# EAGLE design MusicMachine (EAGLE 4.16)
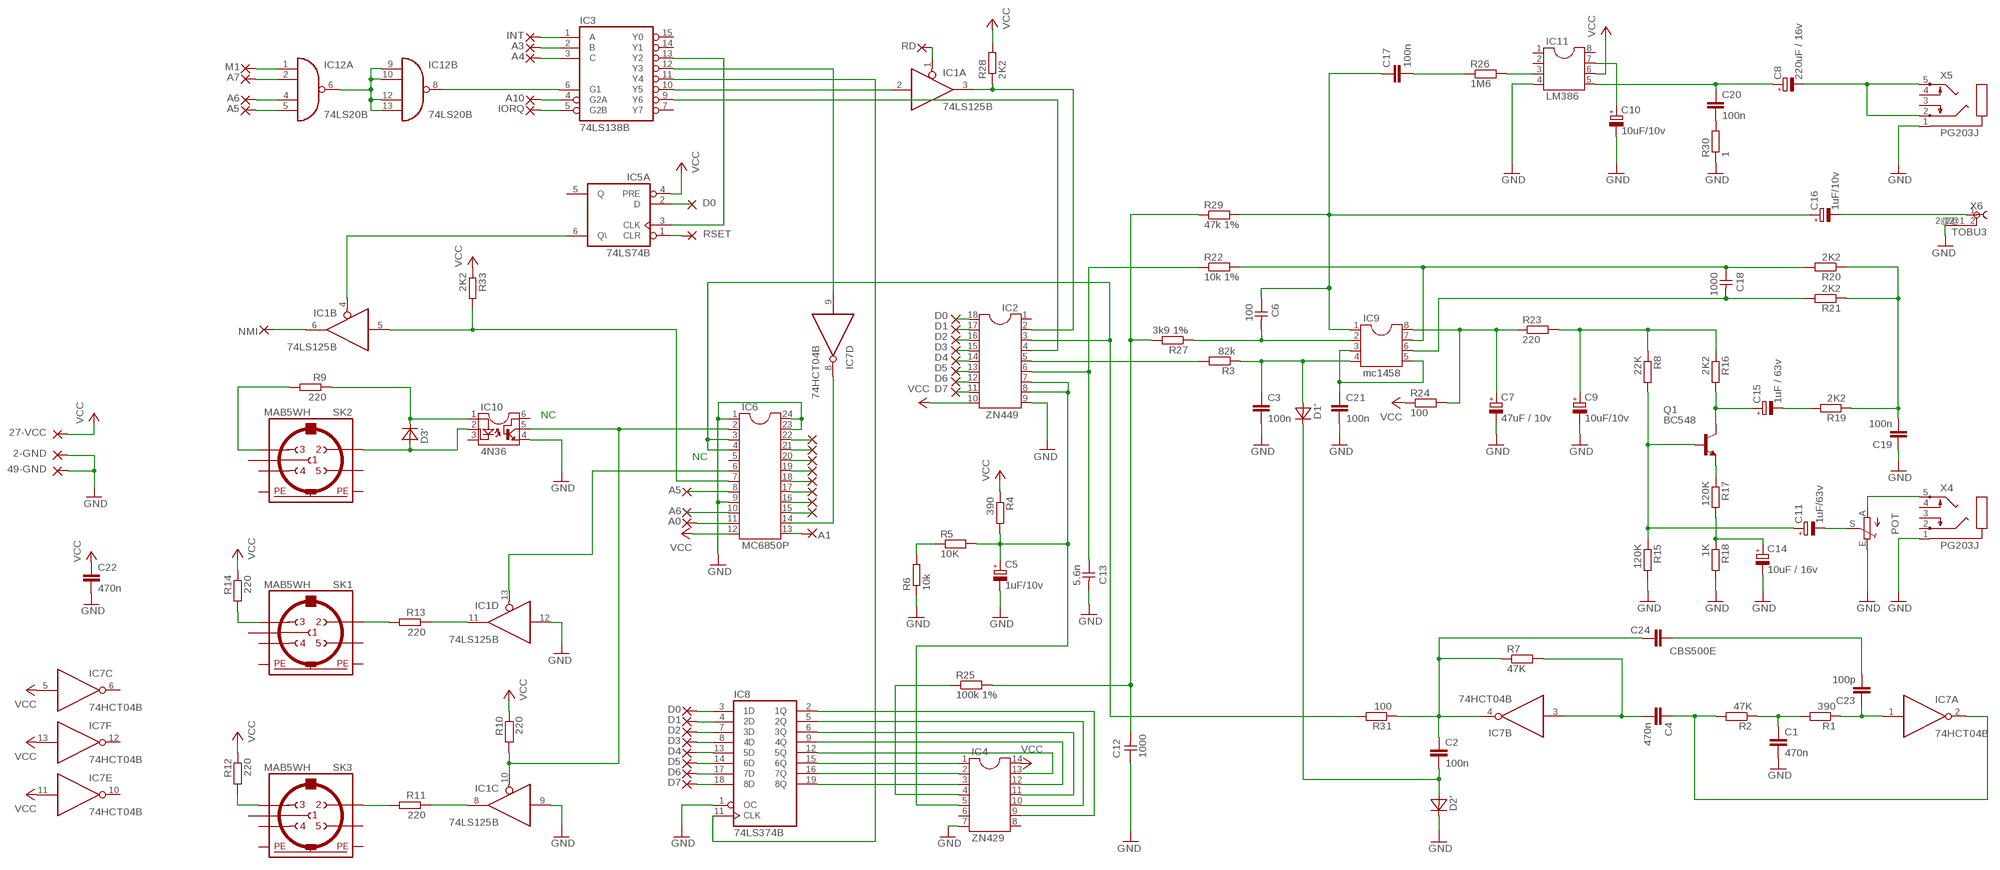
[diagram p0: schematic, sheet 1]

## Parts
2-GND  SMD2  [SMD1,27-2,54]
27-VCC  SMD2  [SMD1,27-2,54]
49-GND  SMD2  [SMD1,27-2,54]
A0  SMD2  [SMD1,27-2,54]
A1  SMD2  [SMD1,27-2,54]
A3  SMD2  [SMD1,27-2,54]
A4  SMD2  [SMD1,27-2,54]
A5  SMD2  [SMD1,27-2,54]
A6  SMD2  [SMD1,27-2,54]
A7  SMD2  [SMD1,27-2,54]
A10  SMD2  [SMD1,27-2,54]
C1  470n  C-EU050-024X044  [C050-024X044]
C2  100n  C-EU050-024X044  [C050-024X044]
C3  100n  C-EU050-024X044  [C050-024X044]
C4  470n  C-EU050-024X044  [C050-024X044]
C5  1uF/10v  CPOL-EUE2.5-5  [E2,5-5]
C6  100  CAPNP-12  [C-12]
C7  47uF / 10v  CPOL-EUE2.5-5  [E2,5-5]
C8  220uF / 16v  CPOL-EUE5-6  [E5-6]
C9  10uF/10v  CPOL-EUE2.5-5  [E2,5-5]
C10  10uF/10v  CPOL-EUE2.5-5  [E2,5-5]
C11  1uF/63v  CPOL-EUE2.5-5  [E2,5-5]
C12  1000  CAPNP-12  [C-12]
C13  5.6n  CAPNP-15  [C-15]
C14  10uF / 16v  CPOL-EUE2.5-5  [E2,5-5]
C15  1uF / 63v  CPOL-EUE2.5-5  [E2,5-5]
C16  1uF/10v  CPOL-EUE2.5-5  [E2,5-5]
C17  100n  C-EU050-024X044  [C050-024X044]
C18  1000  CAPNP-12  [C-12]
C19  100n  C-EU050-024X044  [C050-024X044]
C20  100n  C-EU050-024X044  [C050-024X044]
C21  100n  C-EU050-024X044  [C050-024X044]
C22  470n  C-EU050-024X044  [C050-024X044]
C23  100p  C-EU050-024X044  [C050-024X044]
C24  CBS500E  C-EU050-024X044  [C050-024X044]
D0  SMD2  [SMD1,27-2,54]
D1  SMD2  [SMD1,27-2,54]
D1'  DIODE-10/2  [D-10/2]
D2  SMD2  [SMD1,27-2,54]
D2'  DIODE-10/2  [D-10/2]
D3  SMD2  [SMD1,27-2,54]
D3'  DIODE-10/2  [D-10/2]
D4  SMD2  [SMD1,27-2,54]
D5  SMD2  [SMD1,27-2,54]
D6  SMD2  [SMD1,27-2,54]
D7  SMD2  [SMD1,27-2,54]
IC1  74LS125B  [DIL14-B]
IC2  ZN449  DIL18B  [DIL18B]
IC3  74LS138B  [DIL16-B]
IC4  ZN429  DIL14  [DIL14]
IC5  74LS74B  [DIL14-B]
IC6  MC6850P  DIL24/6B  [DIL24-6B]
IC7  74HCT04B  74LS04B  [DIL14-B]
IC8  74LS374B  [DIL20-B]
IC9  mc1458  DIL8  [DIL08]
IC10  4N36  DIL6  [DIL06]
IC11  LM386  DIL8  [DIL08]
IC12  74LS20B  [DIL14-B]
INT  SMD2  [SMD1,27-2,54]
IORQ  SMD2  [SMD1,27-2,54]
M1  SMD2  [SMD1,27-2,54]
NMI  SMD2  [SMD1,27-2,54]
POT  TRIM_EU-LI15  [LI15]
Q1  BC548  [TO92-EBC]
R1  390  R-EU_0207/10  [0207/10]
R2  47K  R-EU_0207/12  [0207/12]
R3  82k  R-EU_0207/12  [0207/12]
R4  390  R-EU_0207/12  [0207/12]
R5  10K  R-EU_0207/12  [0207/12]
R6  10k  R-EU_0207/12  [0207/12]
R7  47K  R-EU_0207/12  [0207/12]
R8  22K  R-EU_0207/12  [0207/12]
R9  220  R-EU_0207/12  [0207/12]
R10  220  R-EU_0207/12  [0207/12]
R11  220  R-EU_0207/12  [0207/12]
R12  220  R-EU_0207/12  [0207/12]
R13  220  R-EU_0207/12  [0207/12]
R14  220  R-EU_0207/12  [0207/12]
R15  120K  R-EU_0207/12  [0207/12]
R16  2K2  R-EU_0207/12  [0207/12]
R17  120K  R-EU_0207/12  [0207/12]
R18  1K  R-EU_0207/12  [0207/12]
R19  2K2  R-EU_0207/12  [0207/12]
R20  2K2  R-EU_0207/12  [0207/12]
R21  2K2  R-EU_0207/12  [0207/12]
R22  10k 1%  R-EU_0207/12  [0207/12]
R23  220  R-EU_0207/12  [0207/12]
R24  100  R-EU_0207/12  [0207/12]
R25  100k 1%  R-EU_0207/12  [0207/12]
R26  1M6  R-EU_0207/10  [0207/10]
R27  3k9 1%  R-EU_0207/12  [0207/12]
R28  2K2  R-EU_0207/12  [0207/12]
R29  47k 1%  R-EU_0207/12  [0207/12]
R30  1  R-EU_0207/12  [0207/12]
R31  100  R-EU_0207/12  [0207/12]
R33  2K2  R-EU_0207/12  [0207/12]
RD  SMD2  [SMD1,27-2,54]
RSET  SMD2  [SMD1,27-2,54]
SK1  MAB5WH  [MAB5WH]
SK2  MAB5WH  [MAB5WH]
SK3  MAB5WH  [MAB5WH]
X4  PG203J  [PG203J]
X5  PG203J  [PG203J]
X6  TOBU3  [TOBU3]

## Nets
A0: A0.1(P) IC6.11
A1: A1.1(P) IC6.13
A3: A3.1(P) IC3.2(B)
A4: A4.1(P) IC3.3(C)
A5: A5.1(P) IC6.8 IC12.5(A:I3)
A6: A6.1(P) IC6.10 IC12.4(A:I2)
A7: A7.1(P) IC12.2(A:I1)
A10: A10.1(P) IC3.4(G2A)
D0: D0.1(P) IC2.18 IC5.2(A:D) IC6.22 IC8.3(1D)
D1: D1.1(P) IC2.17 IC6.21 IC8.4(2D)
D2: D2.1(P) IC2.16 IC6.20 IC8.7(3D)
D3: D3.1(P) IC2.15 IC6.19 IC8.8(4D)
D4: D4.1(P) IC2.14 IC6.18 IC8.13(5D)
D5: D5.1(P) IC2.13 IC6.17 IC8.14(6D)
D6: D6.1(P) IC2.12 IC6.16 IC8.17(7D)
D7: D7.1(P) IC2.11 IC6.15 IC8.18(8D)
GND: 2-GND.1(P) 49-GND.1(P) C1.2 C3.2 C5.- C7.- C9.- C10.- C12.P$1 C13.2 C14.- C19.1 C21.2 C22.2 D2'.P$4(K) IC1.9(C:I) IC1.12(D:I) IC2.9 IC4.7 IC6.1 IC6.9 IC6.23 IC6.24 IC8.1(OC) IC10.4 IC11.4 POT.E R6.1 R15.2 R18.2 R30.1 X4.1 X5.1 X6.2@2
INT: IC3.1(A) INT.1(P)
IORQ: IC3.5(G2B) IORQ.1(P)
M1: IC12.1(A:I0) M1.1(P)
N$3: IC6.14 IC7.8(D:O)
N$5: C4.1 IC7.2(A:O) R2.2
N$6: C5.+ IC2.7 IC2.8 IC4.5 R4.2 R5.2
N$7: IC12.6(A:O) IC12.9(B:I0) IC12.10(B:I1) IC12.12(B:I2) IC12.13(B:I3)
N$8: C13.1 IC2.6 R22.1
N$9: IC3.6(G1) IC12.8(B:O)
N$11: IC2.4 IC3.9(Y6)
N$12: IC1.2(A:I) IC3.10(Y5)
N$14: IC3.11(Y4) IC8.11(CLK)
N$15: R9.2 SK2.3
N$17: IC3.12(Y3) IC7.9(D:I)
N$22: C23.1 IC7.1(A:I) R1.1
N$23: C23.2 C24.2
N$24: C1.1 R1.2 R2.1
N$25: C2.1 C24.1 IC7.4(B:O) R7.1 R31.1
N$26: IC1.10(C:OE) IC6.2 IC10.5 R10.2
N$27: C4.2 IC7.3(B:I) R7.2
N$28: IC2.3 IC6.3 IC6.4 R31.2
N$29: IC1.13(D:OE) IC6.6
N$30: IC1.5(B:I) IC6.7 R33.2
N$31: IC3.13(Y2) IC5.3(A:CLK)
N$32: IC1.4(B:OE) IC5.6(A:Q\)
N$33: IC1.1(A:OE) RD.1(P)
N$34: IC1.3(A:O) IC2.2 R28.1
N$35: R12.2 SK3.3
N$36: IC4.1 IC8.15(6Q)
N$37: IC2.5 R3.2
N$38: C3.1 D1'.P$3(A) IC9.4 R3.1
N$39: IC4.2 IC8.16(7Q)
N$40: IC4.3 IC8.19(8Q)
N$41: IC4.11 IC8.6(3Q)
N$42: IC4.9 IC8.2(1Q)
N$43: IC4.10 IC8.5(2Q)
N$44: IC4.12 IC8.9(4Q)
N$45: C12.P$2 R25.2 R27.2 R29.1
N$46: IC4.13 IC8.12(5Q)
N$47: IC4.4 R25.1
N$48: C6.P$1 C16.+ C17.1 IC9.1 R29.2
N$49: R5.1 R6.2
N$50: C16.- X6.1
N$51: R14.2 SK1.3
N$52: R13.2 SK1.2
N$53: IC1.11(D:O) R13.1
N$54: IC1.8(C:O) R11.1
N$55: R11.2 SK3.2
N$57: IC1.6(B:O) NMI.1(P)
N$58: D3'.P$4(K) IC10.1 R9.1
N$59: D3'.P$3(A) IC10.2 SK2.2
N$60: C7.+ IC9.8 R23.1 R24.2
N$61: C2.2 D1'.P$4(K) D2'.P$3(A)
N$62: C6.P$2 IC9.2 R27.1
N$63: C8.- X5.2 X5.5
N$64: C21.1 IC9.3 IC9.5
N$81: C20.2 R30.2
N$82: C8.+ C20.1 IC11.5
N$83: IC11.3 R26.2
N$84: C17.2 R26.1
N$85: C10.+ IC11.7
N$86: C9.+ R8.1 R16.1 R23.2
N$87: C11.+ Q1.B R8.2 R15.1
N$88: C11.- POT.S
N$89: POT.A X4.5
N$90: Q1.E R17.1
N$91: C14.+ R17.2 R18.1
N$92: C15.+ Q1.C R16.2
N$93: C19.2 R19.1 R20.1 R21.1
N$94: C18.P$2 IC9.6 R21.2
N$97: C18.P$1 IC9.7 R20.2 R22.2
N$98: C15.- R19.2
RSET: IC5.1(A:CLR) RSET.1(P)
VCC: 27-VCC.1(P) C22.1 IC2.10 IC4.14 IC5.4(A:PRE) IC6.12 IC7.5(C:I) IC7.11(E:I) IC7.13(F:I) IC11.6 R4.1 R10.1 R12.1 R14.1 R24.1 R28.2 R33.1
Unconnected: IC2.1 IC3.7(Y7) IC3.14(Y1) IC3.15(Y0) IC4.6 IC4.8 IC5.5(A:Q) IC5.8(B:Q\) IC5.9(B:Q) IC5.10(B:PRE) IC5.11(B:CLK) IC5.12(B:D) IC5.13(B:CLR) IC6.5 IC7.6(C:O) IC7.10(E:O) IC7.12(F:O) IC10.3 IC10.6 IC11.1 IC11.2 IC11.8 SK1.1 SK1.4 SK1.5 SK2.1 SK2.4 SK2.5 SK3.1 SK3.4 SK3.5 X4.2 X4.3 X4.4 X5.3 X5.4 X6.2 X6.2@1

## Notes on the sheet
- NC
- NC

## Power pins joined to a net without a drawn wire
GND: IC1.7(P:GND) IC3.8(GND) IC5.7(P:GND) IC7.7(P:GND) IC8.10(GND) IC12.7(P:GND)
PE: SK1.PE SK1.PE@(PE) SK2.PE SK2.PE@(PE) SK3.PE SK3.PE@(PE)
VCC: IC1.14(P:VCC) IC3.16(VCC) IC5.14(P:VCC) IC7.14(P:VCC) IC8.20(VCC) IC12.14(P:VCC)

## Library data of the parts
2-GND 27-VCC 49-GND A0 A1 A3-A7 A10 D0 D1-D7 INT IORQ M1 NMI RD RSET = wirepad:SMD2: SMD PAD
C1-C4 C17 C19-C24 = rcl:C-EU: CAPACITOR, European symbol
C5 C7-C11 C14-C16 = rcl:CPOL-EU: POLARIZED CAPACITOR, European symbol
C6 C12 C18 = discrete2:CAPNP-12
C13 = discrete2:CAPNP-15
D1' D2' D3' = discrete2:DIODE-10/2
IC1 = 74xx-eu2:74*125: Quad bus BUFFER, 3-state
IC2 = dil2:DIL18: SOCKET Dual In Line
IC3 = 74xx-eu2:74*138: 3-line to 8-line DECODER/DEMULTIPLEXER
IC4 = dil2:DIL14: SOCKET Dual In Line
IC5 = 74xx-eu2:74*74: Dual D type positive edge triggered FLIP FLOP, preset and clear
IC6 = dil2:DIL24: SOCKET Dual In Line
IC7 = 74xx-eu2:74*04: Hex INVERTER
IC8 = 74xx-eu2:74*374: Octal D type transparent LATCH, edge triggered
IC9 IC11 = dil2:DIL8: SOCKET Dual In Line
IC10 = dil2:DIL6: SOCKET Dual In Line
IC12 = 74xx-eu2:74*20: Dual 4-input NAND gate
POT = pot:TRIM_EU-: POTENTIOMETER
Q1 = transistor-npn:BC548*: NPN Transistor
R1-R31 R33 = rcl:R-EU_: RESISTOR, European symbol
SK1-SK3 = con-hirschmann:MAB5WH: Female CONNECTOR 5 pins with shield, horizontal (DIN 45327)
X4 X5 = con-hirschmann:PG203J: MIC/HEADPHONE JACK KS-S stereo microphone/headphone jack PG203JN (Schukat)
X6 = con-hirschmann:TOBU3: Female Cinch CONNECTOR

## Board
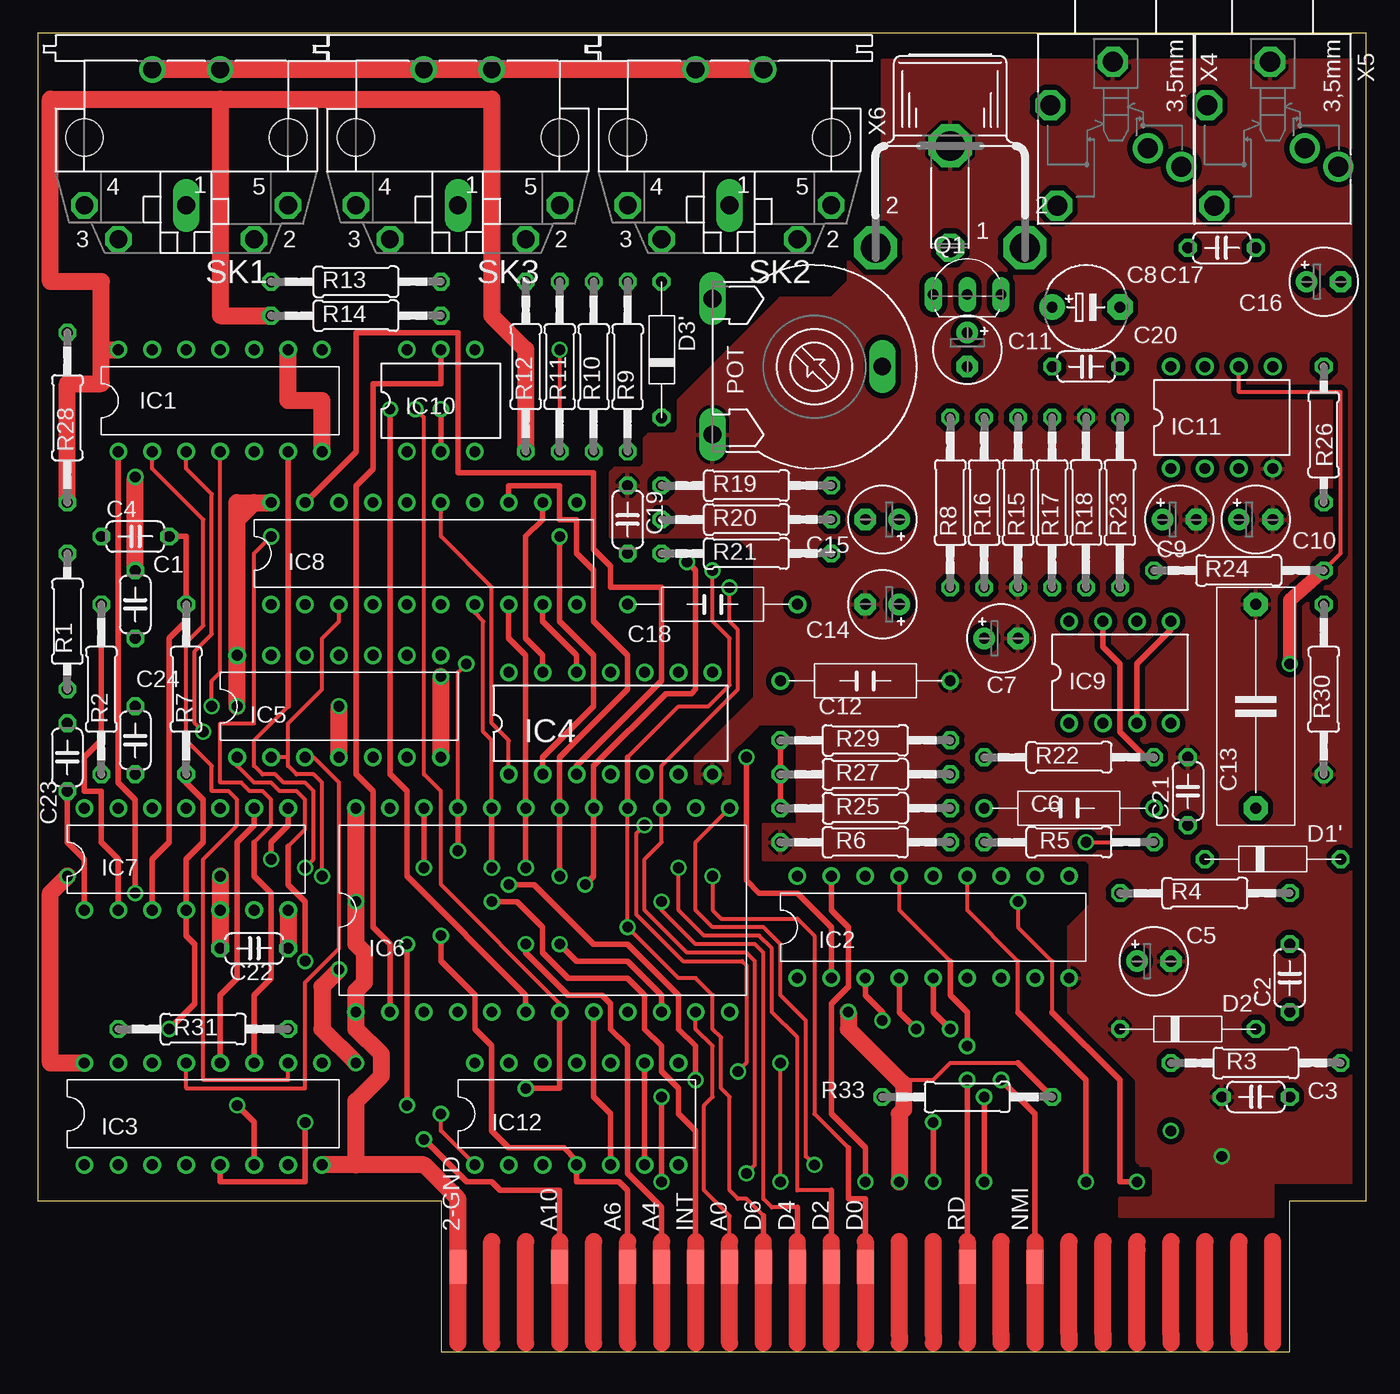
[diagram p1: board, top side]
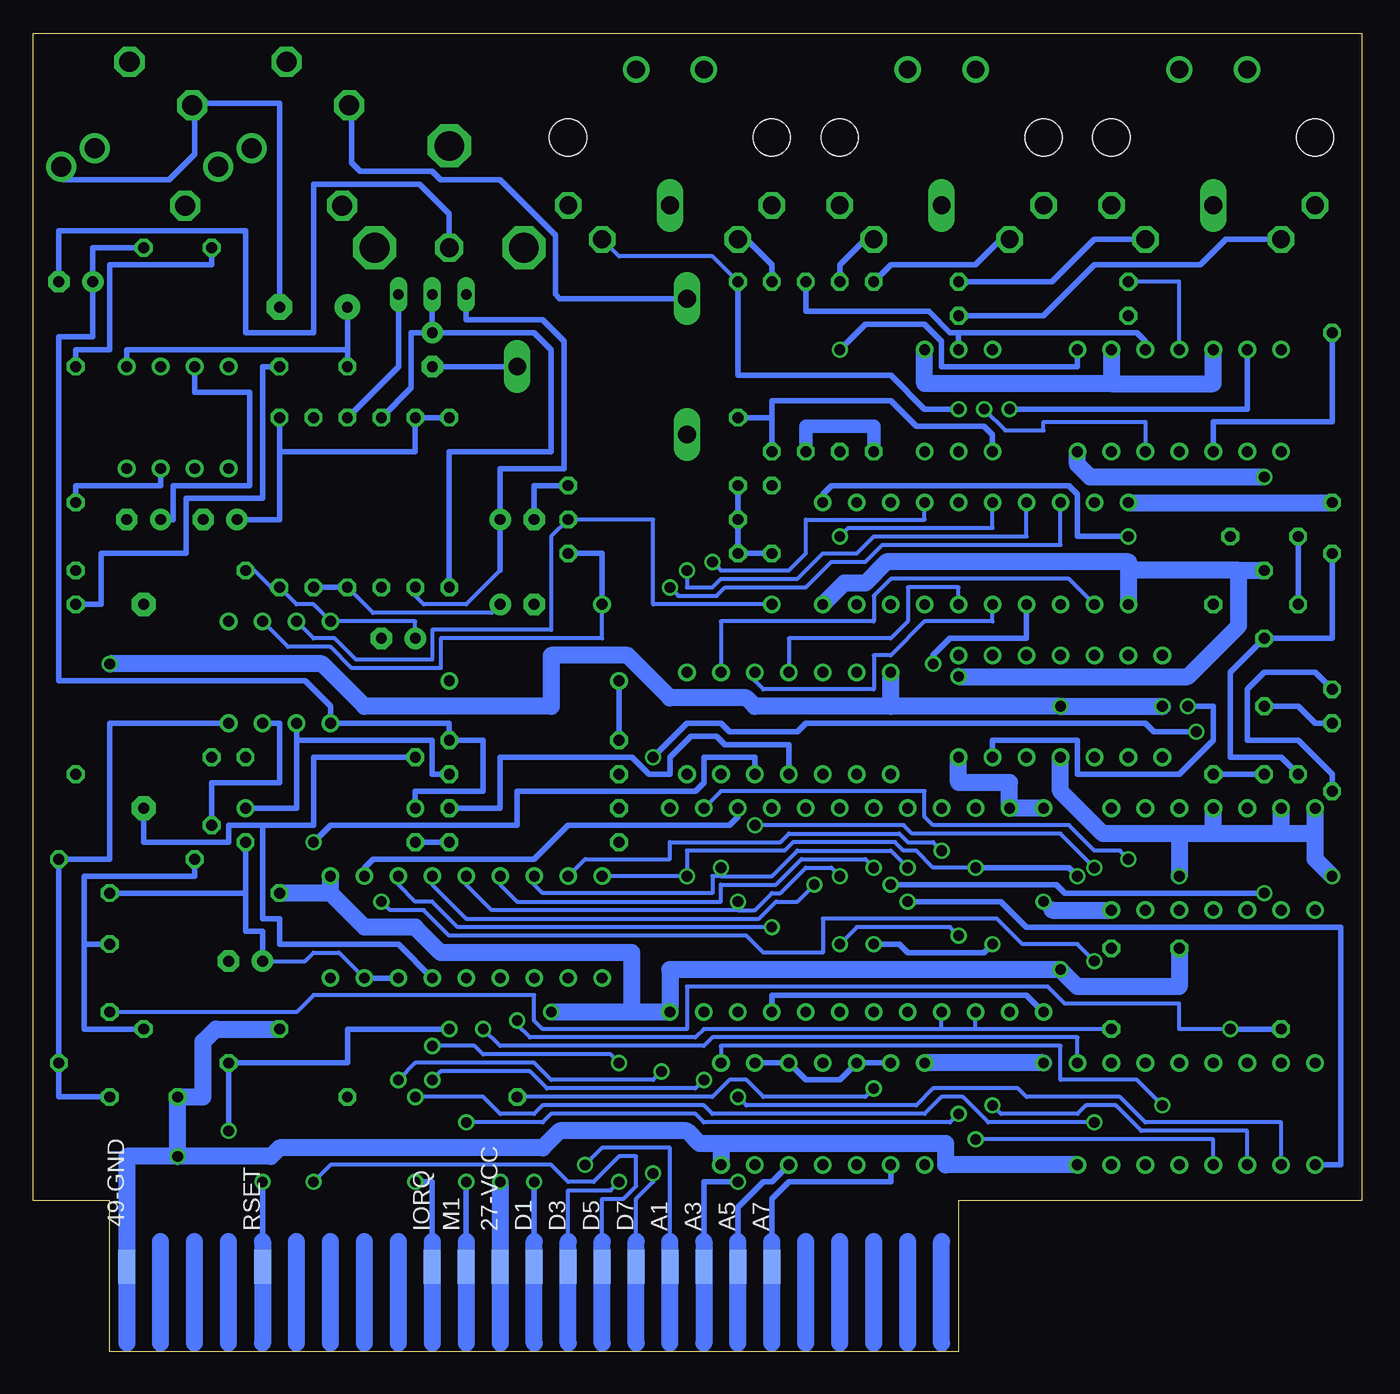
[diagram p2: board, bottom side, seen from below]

Size 99.36 x 98.58 mm. Coordinates in mm from the lower left corner, seen from the top.
Outline: 99.36,98.58 0,98.58 0,11.28 30.15,11.28 30.15,0 93.65,0 93.65,11.28 99.36,11.28 99.36,98.58
Copper layers (1*16): Top 0.035mm / dielectric 1.5mm / Bottom 0.035mm
Design rules "default": minimum track width 10mil, minimum drill 24mil, track to track 8mil, track to pad 8mil, pad to pad 8mil, via to via 8mil, smd to smd 8mil, copper to edge 40mil, drill to drill 8mil, minimum pad ring 10mil, minimum via ring 8mil, stop-mask expansion 4mil, vias tented up to drill 0mil, thermal gap 10mil

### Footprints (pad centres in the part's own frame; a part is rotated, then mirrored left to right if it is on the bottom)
SMD1,27-2,54 = smd 1.27 x 2.54: 1 0,0
C050-024X044 = drill 0.813 octagon: 1 -2.54,0; 2 2.54,0
E2,5-5 = drill 0.813 pad 1.6 round: + -1.27,0 | drill 0.813 pad 1.6 octagon: - 1.27,0
C-12 = drill 0.813 round: P$1 -6.35,0; P$2 6.35,0
E5-6 = drill 0.813 pad 1.905 round: + -2.54,0 | drill 0.813 pad 1.905 octagon: - 2.54,0
C-15 = drill 0.813 pad 1.778 octagon: 1 -7.62,0; 2 7.62,0
D-10/2 = drill 0.813 octagon: P$3 -5.08,0; P$4 5.08,0
DIL14-B = drill 0.813 round: 1 -7.62,-3.81; 2 -5.08,-3.81; 3 -2.54,-3.81; 4 0,-3.81; 5 2.54,-3.81; 6 5.08,-3.81; 7 7.62,-3.81; 8 7.62,3.81; 9 5.08,3.81; 10 2.54,3.81; 11 0,3.81; 12 -2.54,3.81; 13 -5.08,3.81; 14 -7.62,3.81
DIL18B = drill 0.8 round: 1 -10.16,-3.81; 2 -7.62,-3.81; 3 -5.08,-3.81; 4 -2.54,-3.81; 5 0,-3.81; 6 2.54,-3.81; 7 5.08,-3.81; 8 7.62,-3.81; 9 10.16,-3.81; 10 10.16,3.81; 11 7.62,3.81; 12 5.08,3.81; 13 2.54,3.81; 14 0,3.81; 15 -2.54,3.81; 16 -5.08,3.81; 17 -7.62,3.81; 18 -10.16,3.81
DIL16-B = drill 0.813 round: 1 -8.89,-3.81; 2 -6.35,-3.81; 3 -3.81,-3.81; 4 -1.27,-3.81; 5 1.27,-3.81; 6 3.81,-3.81; 7 6.35,-3.81; 8 8.89,-3.81; 9 8.89,3.81; 10 6.35,3.81; 11 3.81,3.81; 12 1.27,3.81; 13 -1.27,3.81; 14 -3.81,3.81; 15 -6.35,3.81; 16 -8.89,3.81
DIL14 = drill 0.813 round: 1 -7.62,-3.81; 2 -5.08,-3.81; 3 -2.54,-3.81; 4 0,-3.81; 5 2.54,-3.81; 6 5.08,-3.81; 7 7.62,-3.81; 8 7.62,3.81; 9 5.08,3.81; 10 2.54,3.81; 11 0,3.81; 12 -2.54,3.81; 13 -5.08,3.81; 14 -7.62,3.81
DIL24-6B = drill 0.8 round: 1 -13.97,-7.62; 2 -11.43,-7.62; 3 -8.89,-7.62; 4 -6.35,-7.62; 5 -3.81,-7.62; 6 -1.27,-7.62; 7 1.27,-7.62; 8 3.81,-7.62; 9 6.35,-7.62; 10 8.89,-7.62; 11 11.43,-7.62; 12 13.97,-7.62; 13 13.97,7.62; 14 11.43,7.62; 15 8.89,7.62; 16 6.35,7.62; 17 3.81,7.62; 18 1.27,7.62; 19 -1.27,7.62; 20 -3.81,7.62; 21 -6.35,7.62; 22 -8.89,7.62; 23 -11.43,7.62; 24 -13.97,7.62
DIL20-B = drill 0.8 round: 1 -11.43,-3.81; 2 -8.89,-3.81; 3 -6.35,-3.81; 4 -3.81,-3.81; 5 -1.27,-3.81; 6 1.27,-3.81; 7 3.81,-3.81; 8 6.35,-3.81; 9 8.89,-3.81; 10 11.43,-3.81; 11 11.43,3.81; 12 8.89,3.81; 13 6.35,3.81; 14 3.81,3.81; 15 1.27,3.81; 16 -1.27,3.81; 17 -3.81,3.81; 18 -6.35,3.81; 19 -8.89,3.81; 20 -11.43,3.81
DIL08 = drill 0.813 round: 1 -3.81,-3.81; 2 -1.27,-3.81; 3 1.27,-3.81; 4 3.81,-3.81; 5 3.81,3.81; 6 1.27,3.81; 7 -1.27,3.81; 8 -3.81,3.81
DIL06 = drill 0.813 round: 1 -2.54,-3.81; 2 0,-3.81; 3 2.54,-3.81; 4 2.54,3.81; 5 0,3.81; 6 -2.54,3.81
LI15 = drill 1.321 long: A -5.08,-7.62; E 5.08,-7.62; S 0,5.08
TO92-EBC = drill 0.813 long: B 0,-1.27; C -2.54,-1.27; E 2.54,-1.27
0207/10 = drill 0.813 octagon: 1 -5.08,0; 2 5.08,0
0207/12 = drill 0.813 octagon: 1 -6.35,0; 2 6.35,0
MAB5WH = drill 1.321 long: 1 0,5.08 | drill 1.321 octagon: 2 -5.08,7.62; 3 5.08,7.62; 4 7.62,5.08; 5 -7.62,5.08 | drill 1.321 round: PE -2.54,-5.08; PE@ 2.54,-5.08 | hole 2.794: 7.62,0; -7.62,0
PG203J = drill 1.499 octagon: 1 -5.004,-0.203; 4 5.74,-4.369; 5 -1.753,-4.902 | drill 1.499 round: 2 2.845,4.902; 3 1.448,2.388
TOBU3 = drill 1.397 octagon: 1 0,-2.54 | drill 2.21 octagon: 2 5.588,-2.54; 2@1 -5.588,-2.54; 2@2 0,5.08

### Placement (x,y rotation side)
2-GND  31.42,6.35 0 top
27-VCC  64.44,6.35 0 bottom
49-GND  92.38,6.35 0 bottom
A0  51.74,6.35 0 top
A1  51.74,6.35 0 bottom
A3  49.2,6.35 0 bottom
A4  46.66,6.35 0 top
A5  46.66,6.35 0 bottom
A6  44.12,6.35 0 top
A7  44.12,6.35 0 bottom
A10  39.04,6.35 0 top
C1  7.29,55.88 90 top
C2  93.65,27.94 90 top
C3  91.11,19.05 180 top
C4  7.29,60.96 0 top
C5  83.49,29.21 0 top
C6  77.14,40.64 0 top
C7  72.06,53.34 0 top
C8  78.41,78.11 0 top
C9  85.39,62.23 0 top
C10  91.11,62.23 0 top
C11  69.52,74.93 270 top
C12  61.9,50.16 180 top
C13  91.11,48.26 90 top
C14  63.17,55.88 180 top
C15  63.17,62.23 180 top
C16  96.19,80.01 0 top
C17  88.57,82.55 180 top
C18  50.47,55.88 0 top
C19  44.12,62.23 270 top
C20  78.41,73.66 0 top
C21  86.03,41.91 90 top
C22  16.18,30.16 0 top
C23  2.21,44.45 90 top
C24  7.29,45.72 90 top
D0  61.9,6.35 0 top
D1  61.9,6.35 0 bottom
D1'  92.38,36.83 180 top
D2  59.36,6.35 0 top
D2'  86.03,24.13 180 top
D3  59.36,6.35 0 bottom
D3'  46.66,74.93 270 top
D4  56.82,6.35 0 top
D5  56.82,6.35 0 bottom
D6  54.28,6.35 0 top
D7  54.28,6.35 0 bottom
IC1  13.64,71.12 0 top
IC2  66.98,31.75 0 top
IC3  12.37,17.78 0 top
IC4  42.85,46.99 0 top
IC5  22.53,48.26 0 top
IC6  37.77,33.02 0 top
IC7  11.1,36.83 0 top
IC8  28.88,59.69 0 top
IC9  80.95,50.8 0 top
IC10  30.15,71.12 0 top
IC11  88.57,69.85 0 top
IC12  40.31,17.78 0 top
INT  49.2,6.35 0 top
IORQ  69.52,6.35 0 bottom
M1  66.98,6.35 0 bottom
NMI  74.6,6.35 0 top
POT  58.09,73.66 270 top
Q1  69.52,80.33 0 top
R1  2.21,54.61 90 top
R2  4.75,49.53 90 top
R3  91.11,21.59 180 top
R4  87.3,34.29 0 top
R5  77.14,38.1 0 top
R6  61.9,38.1 0 top
R7  11.1,49.53 90 top
R8  68.25,63.5 270 top
R9  44.12,73.66 90 top
R10  41.58,73.66 90 top
R11  39.04,73.66 90 top
R12  36.5,73.66 90 top
R13  23.8,80.01 0 top
R14  23.8,77.47 0 top
R15  73.33,63.5 270 top
R16  70.79,63.5 270 top
R17  75.87,63.5 270 top
R18  78.41,63.5 90 top
R19  53.01,64.77 0 top
R20  53.01,62.23 0 top
R21  53.01,59.69 0 top
R22  77.14,44.45 0 top
R23  80.95,63.5 90 top
R24  89.84,58.42 180 top
R25  61.9,40.64 180 top
R26  96.19,68.58 270 top
R27  61.9,43.18 180 top
R28  2.21,69.85 270 top
R29  61.9,45.72 0 top
R30  96.19,49.53 90 top
R31  12.37,24.13 0 top
R33  69.52,19.05 180 top
RD  69.52,6.35 0 top
RSET  82.22,6.35 0 bottom
SK1  11.1,90.81 180 top
SK2  51.74,90.81 180 top
SK3  31.42,90.81 180 top
X4  80.63,91.44 270 top
X5  92.38,91.44 270 top
X6  68.25,85.09 0 top

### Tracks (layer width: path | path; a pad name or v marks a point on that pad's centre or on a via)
A0
  Top 0.305: 51.74,8.26 51.74,10.16 49.83,12.06 49.83,18.41 50.47,19.05 50.47,22.86 49.2,24.13 IC6.11
  Top 1.27: 51.74,0.64 A0.1 51.74,8.26
A1  (via drill 0.8)
  Top 0.305: v58.09,13.97 57.45,14.61 57.45,24.77 55.55,26.67 55.55,30.48 54.28,31.75 50.47,31.75 49.2,33.02 49.2,38.1 IC6.13
  Bottom 0.305: 51.74,8.26 51.74,15.24 56.82,15.24 v58.09,13.97
  Bottom 1.27: 51.74,0.64 A1.1 51.74,8.26
A3  (via drill 0.8)
  Top 0.406: v46.66,19.05 v46.66,12.7
  Bottom 0.305: v46.66,19.05 46.02,18.41 33.32,18.41 32.05,19.68 25.7,19.68 25.07,19.05 18.08,19.05 16.18,17.14 6.02,17.14 IC3.2
  Bottom 0.406: 49.2,8.26 49.2,12.7 v46.66,12.7
  Bottom 1.27: A3.1 49.2,8.26 49.2,0.64
A4  (via drill 0.8)
  Top 0.406: A4.1 46.66,10.79 44.12,13.34 44.12,22.86 42.85,24.13 42.85,26.04 42.21,26.67 39.67,26.67 36.5,29.84 v36.5,30.48 | v27.61,18.41 v27.61,30.48
  Top 1.27: 46.66,0.64 46.66,4.76 A4.1 46.66,8.26
  Bottom 0.305: IC3.3 8.56,16.51 16.5,16.51 18.4,18.41 20.62,18.41 21.26,17.78 26.97,17.78 v27.61,18.41
  Bottom 0.406: v27.61,30.48 28.24,29.84 33.96,29.84 34.59,30.48 v36.5,30.48
A5
  Top 0.406: IC12.5 42.85,17.78 41.58,19.05 IC6.8
  Bottom 0.406: 46.66,8.26 46.66,8.89 | IC12.5 44.12,12.7 44.75,12.7 46.66,10.79 46.66,7.62
  Bottom 1.27: 46.66,0.64 A5.1 46.66,7.62 46.66,8.26
A6  (via drill 0.8)
  Top 0.406: 44.12,7.62 44.12,12.06 43.48,12.7 40.31,12.7 IC12.4 40.31,14.29 39.36,15.24 35.23,15.24 33.96,16.51 33.96,22.86 32.69,24.13 32.69,26.67 30.15,29.21 v30.15,31.11 | v39.04,30.48 40.31,29.21 44.12,29.21 46.66,26.67 IC6.10
  Top 1.27: 44.12,8.26 44.12,7.62 A6.1 44.12,0.64
  Bottom 0.305: v39.04,30.48 37.77,31.75 30.78,31.75 v30.15,31.11
A7
  Bottom 0.406: 44.12,8.26 44.12,11.43 42.85,12.7 35.23,12.7 IC12.2
  Bottom 1.27: 44.12,0.64 A7.1 44.12,8.26
A10  (via drill 0.8)
  Top 0.406: v28.88,15.88 32.05,12.7 33.96,12.7 34.59,12.06 39.04,12.06 39.04,8.26
  Top 1.27: 39.04,0.64 A10.1 39.04,8.26
  Bottom 0.305: IC3.4 11.1,15.88 v28.88,15.88
D0  (via drill 0.8)
  Top 0.305: IC8.3 22.53,54.61 21.26,53.34 21.26,49.53 18.72,46.99 18.72,44.45 | v21.26,35.56 21.26,42.55 20.62,43.18 19.35,43.18 18.72,43.81 18.72,44.45 | 60.63,15.24 58.09,17.78 58.09,31.11 56.82,32.38 51.1,32.38 50.47,33.02 v50.47,35.56 | 18.72,44.45 IC5.2
  Top 0.406: 61.9,8.26 61.9,11.43 60.63,11.43 60.63,15.24 | v28.88,36.2 IC6.22
  Top 1.27: 61.9,0.64 D0.1 61.9,8.26
  Bottom 0.305: v28.88,36.2 32.05,36.2 33.32,37.47 34.28,37.47 34.91,38.1 42.53,38.1 43.17,37.47 50.47,37.47 v50.47,35.56 IC2.18
  Bottom 0.406: v28.88,36.2 21.89,36.2 v21.26,35.56
D1  (via drill 0.8)
  Top 0.305: v32.05,51.44 31.42,50.8 IC6.21
  Top 0.406: v61.9,12.7 61.9,15.24 59.36,17.78 59.36,26.04 60.63,27.3 60.63,31.75 59.36,33.02 IC2.17 | v31.42,37.47 IC6.21
  Bottom 0.305: IC2.17 58.09,36.83 51.74,36.83 51.74,38.1 43.48,38.1 42.85,38.73 34.59,38.73 33.96,38.1 32.05,38.1 v31.42,37.47
  Bottom 0.406: 61.9,8.26 v61.9,12.7 | IC8.4 25.07,53.34 30.78,53.34 32.05,52.07 v32.05,51.44
  Bottom 1.27: 61.9,0.64 D1.1 61.9,8.26
D2  (via drill 0.8)
  Top 0.305: IC8.7 32.69,55.24 33.32,54.61 33.32,46.35 33.96,45.72 IC6.20 | 59.36,12.06 56.82,12.06 56.82,23.5 54.91,25.4 54.91,30.16 53.96,31.11 49.83,31.11 47.93,33.02 v47.93,36.2
  Top 0.406: 59.36,8.26 59.36,12.06 | v33.96,36.2 IC6.20
  Top 1.27: 59.36,0.64 D2.1 59.36,8.26
  Bottom 0.305: IC2.16 61.9,34.92 61.26,34.29 48.56,34.29 48.56,35.56 47.93,35.56 | v47.93,36.2 47.93,35.56 | 47.93,35.56 44.12,35.56 42.21,37.47 35.23,37.47 v33.96,36.2
D3  (via drill 0.8)
  Top 0.305: v55.55,12.7 v55.55,21.59 | IC2.15 64.44,33.02 68.25,29.21
  Top 0.406: IC8.8 35.23,53.34 36.5,52.07 IC6.19 v36.5,36.2 | 68.25,29.21 68.25,26.67 69.52,25.4 v69.52,22.86
  Bottom 0.305: 59.36,8.26 59.36,12.06 56.18,12.06 v55.55,12.7 | IC2.15 64.44,34.92 63.17,33.66 47.93,33.66 47.93,34.92 43.8,34.92 41.89,36.83 37.13,36.83 v36.5,36.2 | v69.52,22.86 66.34,22.86 65.71,22.23 56.18,22.23 v55.55,21.59
  Bottom 1.27: 59.36,0.64 D3.1 59.36,8.26
D4  (via drill 0.8)
  Top 0.305: 56.82,10.79 54.91,10.79 54.28,11.43 54.28,29.84 53.64,30.48 49.2,30.48 46.66,33.02 v46.66,33.66
  Top 0.406: D4.1 56.82,10.79 | IC8.13 35.23,64.77 39.04,64.77 39.04,62.23 40.31,62.23 40.31,59.69 41.58,58.42 41.58,54.61 44.12,52.07 44.12,49.53 39.04,44.45 IC6.18 v39.04,35.56
  Top 1.27: 56.82,0.64 D4.1 56.82,8.26
  Bottom 0.305: IC2.14 66.98,34.92 65.07,33.02 46.66,33.02 | v46.66,33.66 46.66,33.02 | 46.66,33.02 45.39,33.02 44.12,34.29 43.48,34.29 41.58,36.2 39.67,36.2 v39.04,35.56
D5  (via drill 0.8)
  Top 0.305: 73.33,25.4 73.33,29.21 69.52,33.02 IC2.13
  Top 0.406: v48.56,59.05 49.2,58.42 49.2,49.53 48.88,49.21 46.97,49.21 41.58,43.81 IC6.17 41.58,35.56 v40.94,34.92 | v78.41,12.7 78.41,20.32 73.33,25.4
  Bottom 0.305: 56.82,8.26 56.82,11.43 55.23,11.43 54.28,12.38 54.28,14.61 55.55,14.61 57.45,12.7 59.36,12.7 60.63,13.97 77.14,13.97 v78.41,12.7 | IC8.14 32.69,62.23 41.58,62.23 41.58,59.69 42.85,58.42 47.93,58.42 v48.56,59.05 | v40.94,34.92 42.21,33.66 43.8,33.66 45.07,32.38 66.98,32.38 69.52,34.92 IC2.13
  Bottom 1.27: 56.82,0.64 D5.1 56.82,8.26
D6  (via drill 0.8)
  Top 0.305: 54.28,10.16 53.01,11.43 52.37,11.43 51.74,12.06 51.74,19.05 51.1,19.68 51.1,23.5 50.47,24.13 50.47,26.67 49.2,27.94 47.93,27.94 v44.12,31.75 IC6.16 | v50.47,58.42 50.47,54.61 51.74,53.34 51.74,49.85 50.15,48.26 47.93,48.26 44.12,44.45
  Top 0.406: 54.28,8.26 54.28,10.16 | IC6.16 44.12,44.45
  Top 1.27: 54.28,0.64 D6.1 54.28,8.26
  Bottom 0.305: IC8.17 25.07,60.96 36.5,60.96 37.77,59.69 40.31,59.69 42.21,57.78 47.93,57.78 48.56,57.15 50.47,57.15 v50.47,58.42 | IC2.12 72.06,34.92 70.79,33.66 69.52,33.66 67.61,31.75 v44.12,31.75
D7  (via drill 0.8)
  Top 0.305: v53.01,13.34 53.64,13.97 53.64,29.21 53.01,29.84 48.56,29.84 45.39,33.02 45.39,36.83 46.66,38.1 IC6.15 46.66,43.81 52.37,49.53 52.37,53.98 51.74,54.61 v51.74,57.15
  Bottom 0.305: 54.28,8.26 54.28,11.43 53.01,12.7 v53.01,13.34 | IC8.18 22.53,60.33 35.86,60.33 37.13,59.05 39.67,59.05 41.58,57.15 47.61,57.15 48.25,56.52 51.1,56.52 v51.74,57.15
  Bottom 0.406: IC2.11 74.6,36.2 73.96,36.83 61.9,36.83 59.36,39.37 47.29,39.37 46.66,40.01 IC6.15
  Bottom 1.27: 54.28,0.64 D7.1 54.28,8.26
GND  (via drill 0.8)
  Top 1.27: 31.42,0.64 2-GND.1 31.42,8.26 31.42,11.43 28.88,13.97 23.8,13.97 | 23.8,13.97 IC3.8 | IC5.7 v30.15,50.48 | IC7.7 C22.2 | IC6.24 v23.8,33.66 23.8,30.48 24.43,29.84 24.43,27.62 23.8,26.99 IC6.1 23.8,24.13 25.7,22.23 25.7,20.64 23.8,18.73 23.8,13.97 | C1.2 v7.29,65.41 | IC1.7 21.26,71.12 18.72,71.12 IC1.9
  Bottom 0.406: IC6.9 44.12,26.67 25.07,26.67 IC6.1
  Bottom 1.016: 17.45,58.42 17.45,59.05 | v23.8,33.66 23.16,33.02
  Bottom 1.27: IC3.8 31.1,13.97 31.1,15.56 47.93,15.56 | 47.93,15.56 IC12.7 | 47.93,15.56 49.51,15.56 50.47,16.51 59.99,16.51 61.26,15.24 80.95,15.24 81.58,14.61 v88.57,14.61 | v88.57,14.61 92.38,14.61 49-GND.1 92.38,0.64 | IC8.1 17.45,58.42 9.19,58.42 | 17.45,59.05 35.54,59.05 37.13,57.47 38.72,57.47 IC8.10 | 9.19,58.42 9.19,54.29 13,50.48 v30.15,50.48 | IC5.7 30.15,42.55 26.34,42.55 IC6.23 IC6.24 | 23.16,33.02 IC7.7 | 9.19,58.42 C1.2 | IC1.7 21.26,66.36 20.3,65.41 v7.29,65.41 | v88.57,14.61 C3.2 86.66,19.05 86.66,23.18 85.71,24.13 D2'.P$4 | IC1.12 11.1,72.39 18.72,72.39 | IC1.9 18.72,72.39 | IC10.4 32.69,72.39 18.72,72.39
  pour Top (isolate 0.406): 80.95,10.16 92.38,10.16 92.38,12.7 98.73,12.7 98.73,96.52 63.17,96.52 63.17,82.55 60.63,82.55 60.63,80.01 59.36,78.74 55.55,78.74 47.93,71.12 47.93,68.9 47.61,68.58 45.7,68.58 45.39,68.26 45.39,66.36 45.07,66.04 43.16,66.04 42.85,65.72 42.85,60.96 52.37,60.96 53.64,59.69 53.64,48.9 49.2,44.45 49.2,42.55 51.74,42.55 51.74,44.77 53.64,46.67 53.96,46.99 56.5,46.99 56.82,46.67 56.82,39.37 54.28,39.37 54.28,36.83 78.41,36.83 78.73,36.51 78.73,33.34 77.14,31.75 77.14,25.4 82.22,20.32 82.22,14.29 82.54,13.97 83.17,13.97 83.49,13.65 83.49,11.75 83.17,11.43 80.95,11.43
INT  (via drill 0.8)
  Top 0.406: 49.2,8.26 49.2,16.51 47.93,17.78 47.93,19.68 46.66,20.95 46.66,22.86 45.39,24.13 45.39,26.67 44.12,27.94 39.67,27.94 37.77,29.84 37.77,31.75 35.86,33.66 v33.96,33.66
  Top 1.27: 49.2,0.64 INT.1 49.2,8.26
  Bottom 0.406: IC3.1 1.57,13.97 1.57,31.75 25.07,31.75 26.97,33.66 v33.96,33.66
IORQ  (via drill 0.8)
  Top 0.406: v70.79,19.05 v70.79,12.7 | IC3.5 13.64,12.7 19.99,12.7 v19.99,17.14
  Bottom 0.305: v70.79,19.05 65.71,19.05 64.44,17.78 61.9,17.78 61.26,18.41 49.2,18.41 48.56,17.78 32.69,17.78 31.42,19.05 29.83,19.05 27.93,17.14 v19.99,17.14
  Bottom 0.406: 69.52,8.26 69.52,12.7 v70.79,12.7
  Bottom 1.27: 69.52,0.64 IORQ.1 69.52,8.26
M1  (via drill 0.8)
  Top 0.305: v30.15,17.78 30.15,16.51 IC12.1
  Top 0.406: v66.98,17.14 v66.98,12.7
  Bottom 0.305: v66.98,17.14 61.26,17.14 60.63,17.78 49.83,17.78 49.2,17.14 30.78,17.14 v30.15,17.78
  Bottom 0.406: v66.98,12.7 66.98,8.26
  Bottom 1.27: 66.98,0.64 M1.1 66.98,8.26
N$1
  Top 1.27: 92.38,8.26 92.38,7.62 92.38,0.64
N$2
  Top 1.27: 41.58,0.64 41.58,8.26
N$3  (via drill 0.8)
  Top 0.406: v17.45,36.83 17.45,38.1 18.72,39.37 IC7.8
  Bottom 0.305: IC6.14 47.93,41.91 32.69,41.91 32.69,40.01 32.05,39.37 21.89,39.37 19.99,37.47 18.08,37.47 v17.45,36.83
N$4
  Top 1.27: 36.5,0.64 36.5,8.26
N$5
  Top 0.406: IC7.2 6.02,36.83 4.75,38.1 4.75,41.91 3.48,41.91 3.48,44.45 4.75,45.72 R2.2
  Bottom 0.406: R2.2 C4.1
N$6  (via drill 0.8)
  Top 0.305: v78.41,38.1 R5.2
  Bottom 0.305: IC2.8 76.5,29.84 78.41,29.84 79.04,29.21 C5.+
  Bottom 0.406: IC4.5 45.39,44.45 49.2,44.45 49.2,42.55 49.83,41.91 63.17,41.91 63.17,39.37 77.14,39.37 v78.41,38.1 | IC2.8 IC2.7 | C5.+ 82.22,31.43 83.49,31.43 83.49,34.29 | R5.2 83.49,34.29 | 83.49,34.29 R4.2
N$7
  Top 0.406: IC12.9 IC12.6
  Bottom 0.406: IC12.13 IC12.12 39.04,20.32 41.58,20.32 IC12.10 IC12.9
N$8
  Bottom 0.406: IC2.6 72.06,30.48 80.95,30.48 80.95,32.38 82.22,32.38 82.22,39.37 | 82.22,39.37 84.76,39.37 84.76,38.1 91.11,38.1 C13.1 | 82.22,39.37 78.41,39.37 78.41,44.45 R22.1
N$9  (via drill 0.8)
  Top 0.406: v14.91,18.41 16.18,17.14 IC3.6
  Bottom 0.305: IC12.8 47.93,22.86 22.53,22.86 22.53,20.32 16.81,20.32 v14.91,18.41
N$10
  Bottom 1.27: 31.42,0.64 31.42,8.26
N$11  (via drill 0.8)
  Top 0.406: v65.71,24.13 64.44,25.4 IC2.4
  Bottom 0.305: IC3.9 21.26,23.5 48.56,23.5 49.2,22.86 64.44,22.86 v65.71,24.13
N$12
  Top 0.305: IC3.10 18.72,20.32 12.37,20.32 12.37,36.83 14.91,39.37 14.91,41.27 14.27,41.91 13,41.91 13,43.81 11.1,45.72 11.1,53.02 12.37,54.29 12.37,62.23 8.56,66.04 IC1.2
N$13
  Bottom 1.27: 41.58,0.64 41.58,8.26
N$14  (via drill 0.8)
  Top 0.305: 16.18,38.1 17.45,39.37 17.45,41.27 16.81,41.91 15.86,41.91 15.22,42.55 13.64,42.55 13.64,46.99 16.18,46.99 16.18,59.69 v17.45,60.96
  Top 0.406: IC3.11 16.18,26.67 17.45,27.94 17.45,34.29 16.18,35.56 16.18,38.1
  Bottom 0.406: IC8.11 40.31,64.14 39.67,64.77 21.89,64.77 21.26,64.14 21.26,60.96 v17.45,60.96
N$15
  Bottom 0.406: SK2.3 46.02,83.19 44.12,81.28 R9.2
N$17
  Top 0.406: IC3.12 13.64,26.67 14.91,27.94 14.91,38.1 16.18,39.37 IC7.9
N$18
  Bottom 1.27: 39.04,0.64 39.04,8.26
N$19
  Bottom 1.27: 36.5,0.64 36.5,8.26
N$20
  Bottom 1.27: 33.96,0.64 33.96,8.26
N$21
  Top 1.27: 33.96,0.64 33.96,8.26
N$22
  Top 0.406: IC7.1 3.48,36.83 2.21,38.1 C23.1
  Bottom 0.406: C23.1 2.21,43.18 4.75,45.72 8.56,45.72 8.56,49.53 7.29,50.8 3.48,50.8 R1.1
N$23
  Bottom 0.406: C23.2 3.48,46.99 4.75,48.26 C24.2
N$24
  Bottom 0.406: R1.2 2.21,53.34 C1.1 9.83,50.8 9.83,44.45 6.02,44.45 R2.1
N$25  (via drill 0.8)
  Top 0.406: v9.83,24.13 11.73,26.04 11.73,30.48 11.1,31.11 IC7.4 11.1,36.83 12.37,38.1 12.37,41.27 11.1,42.55 R7.1
  Bottom 0.305: v9.83,24.13 13.64,24.13 13.64,26.04 22.21,26.04 23.48,27.3 50.47,27.3 50.47,24.13 61.26,24.13 61.9,24.77 61.9,26.67 78.41,26.67 79.68,25.4 C2.1
  Bottom 0.406: R7.1 C24.1 | R31.1 v9.83,24.13
N$26
  Top 0.406: IC10.5 30.15,72.39 25.07,72.39 25.07,66.04 23.8,64.77 23.8,43.18 25.07,41.91 25.07,31.75 26.34,30.48 IC6.2
  Bottom 0.406: IC1.10 16.18,75.56 16.81,76.2 30.15,76.2 | 30.15,76.2 30.78,76.2 32.37,77.79 41.58,77.79 R10.2 | IC10.5 30.15,76.2
N$27
  Top 0.406: C4.2 11.1,60.96 R7.2 11.1,54.61 9.83,53.34 9.83,38.1 8.56,36.83 IC7.3
N$28  (via drill 0.8)
  Top 0.406: v63.17,24.77 63.17,25.4 61.9,26.67 IC2.3
  Bottom 0.305: R31.2 28.88,24.13 | 28.88,24.13 31.42,24.13 | 31.42,24.13 49.2,24.13 49.83,23.5 62.21,23.5 63.17,24.45 v63.17,24.77 | 31.42,24.13 IC6.4 | 28.88,24.13 IC6.3
N$29  (via drill 0.8)
  Top 0.406: v26.34,70.48 26.34,43.18 27.61,41.91 27.61,35.56 36.5,26.67 IC6.6
  Bottom 0.406: IC1.13 8.56,70.48 v26.34,70.48
N$30  (via drill 0.8)
  Top 0.305: v28.24,70.48 28.88,69.85 28.88,43.18 30.15,41.91 30.15,34.92 39.04,26.04 IC6.7
  Top 0.406: IC6.7 39.04,19.68 v36.5,19.68
  Bottom 0.305: v36.5,19.68 37.13,19.05 44.75,19.05 46.02,20.32 47.29,20.32 48.56,19.05 R33.2 | IC1.5 16.18,69.53 23.8,69.53 23.8,68.9 26.66,68.9 v28.24,70.48
N$31
  Top 0.305: IC3.13 11.1,19.68 19.99,19.68 19.99,27.62 22.53,30.16 22.53,42.55 20.62,44.45 IC5.3
N$32  (via drill 0.8)
  Top 0.305: v13,48.26 13,50.16 13.64,50.8 IC1.4
  Bottom 0.406: IC5.6 27.61,45.72 21.26,45.72 21.26,43.18 13.64,43.18 11.1,45.72 11.1,48.26 v13,48.26
N$33  (via drill 0.8)
  Top 0.406: v69.52,20.32 69.52,8.26 | v49.2,20.32 49.2,22.86 47.93,24.13 47.93,26.67 44.12,30.48 41.58,30.48 37.13,34.92 v35.23,34.92 | IC1.1 6.02,42.55 7.29,41.27 v7.29,34.29
  Top 1.27: 69.52,0.64 RD.1 69.52,8.26
  Bottom 0.305: v69.52,20.32 68.88,20.95 62.21,20.95 60.95,19.68 49.83,19.68 v49.2,20.32
  Bottom 0.406: v7.29,34.29 22.21,34.29 22.84,34.92 v35.23,34.92
N$34  (via drill 0.8)
  Top 0.305: IC1.3 11.1,66.04 13,64.14 13,53.66 11.73,52.39 11.73,46.99 v12.37,46.35
  Top 0.406: v53.01,44.45 53.01,35.24 53.96,34.29 56.82,34.29 59.36,31.75 IC2.2
  Bottom 0.406: v12.37,46.35 15.54,46.35 16.18,46.99 41.58,46.99 42.21,46.35 47.29,46.35 47.93,46.99 50.47,46.99 v53.01,44.45 | IC1.3 11.1,69.53 2.21,69.53 R28.1
N$35
  Bottom 0.406: SK3.3 26.97,83.19 28.88,81.28 35.23,81.28 R12.2
N$36
  Top 0.305: IC4.1 35.23,45.72 33.96,46.99 33.96,57.15 30.15,60.96 IC8.15
N$37  (via drill 0.8)
  Top 0.406: IC2.5 66.98,25.4 v68.25,24.13
  Bottom 0.406: v68.25,24.13 75.87,24.13 75.87,21.59 R3.2 v84.76,16.51
N$38
  Bottom 0.406: C3.1 97.46,19.05 R3.1 D1'.P$3 93.65,36.83 93.65,46.99 IC9.4
N$39  (via drill 0.8)
  Top 0.406: IC4.2 37.77,44.45 41.58,48.26 41.58,52.07 39.04,54.61 v39.04,60.96
  Bottom 0.305: IC8.16 27.61,61.59 38.4,61.59 v39.04,60.96
N$40
  Top 0.305: IC4.3 40.31,43.81
  Top 0.406: IC8.19 23.8,67.31 23.8,76.2 31.42,76.2 31.42,65.72 41.58,65.72 41.58,60.01 42.85,58.74 42.85,57.15 46.66,57.15 46.66,50.16 40.31,43.81
N$41
  Bottom 0.305: IC4.11 42.85,53.34 35.23,53.34 33.96,54.61 33.96,57.15 30.15,57.15 IC8.6
N$42
  Bottom 0.305: IC4.9 47.93,54.61 36.5,54.61 36.5,56.52 35.23,57.78 21.89,57.78 IC8.2
N$43
  Bottom 0.305: IC4.10 45.39,50.16 44.75,49.53 36.5,49.53 36.5,52.07 35.23,52.07 32.69,54.61 27.61,54.61 IC8.5
N$44
  Top 0.406: IC4.12 40.31,52.07 37.77,54.61 IC8.9
N$45
  Top 0.406: R25.2 R27.2 R29.1
  Bottom 0.406: R29.1 C12.P$2
N$46
  Top 0.406: IC4.13 37.77,52.07 36.5,53.34 36.5,60.96 37.77,62.23 IC8.12
N$47
  Bottom 0.406: IC4.4 42.85,45.4 47.61,45.4 48.25,46.04 50.15,46.04 51.74,44.45 51.74,43.18 53.32,43.18 54.6,44.45 64.44,44.45 64.44,40.64 R25.1
N$48
  Bottom 0.406: C6.P$1 70.79,41.91 65.71,41.91 65.71,45.72 R29.2 68.25,46.99 IC9.1 77.14,48.26 79.04,50.16 97.46,50.16 97.46,75.88 94.92,75.88 C16.+ 94.92,82.55 C17.1
N$49
  Bottom 0.406: R6.2 R5.1
N$50
  Bottom 0.406: C16.- 97.46,83.82 83.49,83.82 83.49,76.2 78.41,76.2 78.41,87.31 70.47,87.31 68.25,85.09 X6.1
N$51
  Bottom 0.406: SK1.3 10.14,83.19 12.05,81.28 19.99,81.28 23.8,77.47 R14.2
N$52
  Bottom 0.406: SK1.2 19.99,83.19 23.16,80.01 R13.2
N$53
  Bottom 0.305: R13.1 13.64,80.01 IC1.11
N$54  (via drill 0.8)
  Top 0.305: v39.04,74.93 R11.1
  Bottom 0.406: IC1.8 21.26,73.66 31.42,73.66 31.42,75.56 32.69,76.83 37.13,76.83 v39.04,74.93
N$55
  Bottom 0.406: SK3.2 37.13,83.19 39.04,81.28 R11.2
N$57  (via drill 0.8)
  Top 0.305: v52.37,20.95 53.01,21.59 53.01,28.89 52.69,29.21 48.25,29.21 44.75,32.7 44.75,38.73 v45.39,39.37 | 18.72,48.26 16.18,45.72 16.18,43.81 16.81,43.18 17.77,43.18 18.4,42.55 19.99,42.55 20.62,41.91 20.62,36.83 v19.99,36.2
  Top 0.406: 74.6,8.26 74.6,17.78 v72.06,20.32 | 18.72,48.26 IC1.6
  Top 1.27: 74.6,0.64 NMI.1 74.6,8.26
  Bottom 0.305: v72.06,20.32 70.79,21.59 61.9,21.59 60.63,20.32 53.01,20.32 v52.37,20.95 | v19.99,36.2 22.53,38.73 33.64,38.73 34.28,39.37 v45.39,39.37
N$58
  Bottom 0.406: 44.12,69.85 44.12,71.12 35.23,71.12 33.32,69.22 28.24,69.22 27.61,68.58 IC10.1 | 44.12,69.85 R9.1 | 44.12,69.85 D3'.P$4
N$59  (via drill 0.8)
  Top 0.406: IC10.2 v30.15,70.48
  Bottom 0.305: SK2.2 55.55,81.92 48.56,81.92 D3'.P$3
  Bottom 0.406: D3'.P$3 46.66,73.03 35.23,73.03 32.69,70.48 v30.15,70.48
N$60
  Bottom 0.305: R24.2 82.85,58.42 81.58,57.15 R23.1 79.68,55.88 78.41,55.88 IC9.8 70.79,54.61 C7.+
N$61
  Bottom 0.406: D2'.P$3 95.55,24.13 95.55,30.48 | 95.55,30.48 95.55,35.56 87.3,35.56 D1'.P$4 | 95.55,30.48 C2.2
N$62
  Bottom 0.406: C6.P$2 79.68,40.64 79.68,45.72 | 79.68,45.72 IC9.2 | R27.1 69.52,43.18 69.52,45.72 79.68,45.72
N$63
  Bottom 0.305: 87.62,93.34 87.48,92.85 X5.5 | 97.14,87.63 97.28,87.77
  Bottom 0.406: C8.- 80.95,93.34 87.62,93.34 87.3,92.39 87.3,89.53 89.2,87.63 97.14,87.63 | 97.28,87.77 X5.2
N$64
  Top 0.406: IC9.5 84.76,53.98 82.22,51.44 IC9.3
  Bottom 0.406: IC9.3 80.95,46.99 80.95,42.55 86.03,42.55 C21.1
N$65
  Top 1.27: 89.84,0.64 89.84,1.27 89.84,8.26
N$66
  Top 1.27: 87.3,0.64 87.3,8.26
N$67
  Top 1.27: 84.76,0.64 84.76,1.27 84.76,8.26
N$68
  Top 1.27: 82.22,8.26 82.22,7.62 82.22,0.64
N$69
  Top 1.27: 79.68,0.64 79.68,1.27 79.68,8.26
N$70
  Top 1.27: 77.14,0.64 77.14,1.27 77.14,8.26
N$71
  Top 1.27: 72.06,0.64 72.06,1.27 72.06,8.26
N$72
  Top 1.27: 66.98,0.64 66.98,1.27 66.98,8.26
N$73
  Top 1.27: 64.44,0.64 64.44,1.27 64.44,8.26
N$74
  Bottom 1.27: 72.06,0.64 72.06,8.26
N$75
  Bottom 1.27: 74.6,0.64 74.6,8.26
N$76
  Bottom 1.27: 77.14,0.64 77.14,8.26
N$77
  Bottom 1.27: 79.68,0.64 79.68,8.26
N$78
  Bottom 1.27: 84.76,0.64 84.76,8.26
N$79
  Bottom 1.27: 87.3,0.64 87.3,8.26
N$80
  Bottom 1.27: 89.84,0.64 89.84,8.26
N$81
  Bottom 0.406: R30.2 94.28,55.88 94.28,59.69 87.93,59.69 87.93,63.82 82.22,63.82 82.22,73.66 C20.2
N$82
  Bottom 0.406: C20.1 75.87,74.93 | 75.87,74.93 C8.+ | IC11.5 92.38,74.93 75.87,74.93
N$83
  Bottom 0.406: IC11.3 89.84,64.77 96.19,64.77 R26.2
N$84
  Bottom 0.406: R26.1 96.19,74.93 93.65,74.93 93.65,81.28 86.03,81.28 C17.2
N$85
  Bottom 0.406: C10.+ 88.89,62.23 88.89,64.77 83.17,64.77 83.17,71.75 87.3,71.75 IC11.7
N$86
  Bottom 0.406: C9.+ 80.95,62.23 80.95,67.31 | 80.95,67.31 R23.2 | 80.95,67.31 70.79,67.31 R16.1 R8.1
N$87
  Bottom 0.406: R8.2 68.25,67.31 60.63,67.31 60.63,74.93 61.9,76.2 C11.+ | C11.+ Q1.B | C11.+ 71.11,76.2 71.11,72.07 R15.1
N$88
  Bottom 0.406: POT.S C11.-
N$89
  Bottom 0.305: 75.55,93.03 75.4,93.19 X4.5
  Bottom 0.406: POT.A 59.99,78.74 60.31,79.06 60.31,83.5 64.44,87.63 68.88,87.63 69.52,88.27 74.92,88.27 75.55,88.9 75.55,93.03
N$90
  Bottom 0.406: Q1.E 72.06,73.66 R17.1
N$91
  Bottom 0.305: C14.+ 65.07,55.24 73.96,55.24 R17.2
  Bottom 0.406: R17.2 R18.1
N$92
  Bottom 0.305: R16.2 70.79,56.52 70.15,55.88 66.98,55.88 64.44,58.42
  Bottom 0.406: 64.44,58.42 C15.+ 64.44,66.04 59.68,66.04 59.68,75.56 61.26,77.15 66.98,77.15 Q1.C
N$93
  Bottom 0.406: R19.1 R20.1 R21.1 C19.2
N$94
  Bottom 0.305: IC9.6 80.31,52.7 77.14,52.7 75.55,51.12 68.88,51.12 68.88,53.34 56.82,53.34 C18.P$2
  Bottom 0.406: R21.2 56.82,59.69 C18.P$2
N$97
  Top 0.406: R22.2 82.85,44.45 80.95,46.35 80.95,51.44 79.68,52.7 IC9.7
  Bottom 0.305: IC9.7 78.41,53.34 76.82,53.34 75.23,51.75 69.52,51.75 69.52,53.98 60.63,53.98 60.63,60.96 R20.2 53.01,62.23 53.01,55.88 C18.P$1
N$98
  Bottom 0.406: R19.2 61.9,64.77 C15.-
PE
  Top 1.27: SK1.PE@ SK1.PE SK3.PE@ SK3.PE SK2.PE@ SK2.PE
RSET  (via drill 0.8)
  Top 0.305: IC5.1 14.91,43.81 16.18,42.55 17.45,42.55 18.08,41.91 19.35,41.91 19.99,41.27 19.99,39.05 18.72,37.78 | v73.33,33.66 73.33,31.75 75.87,29.21 75.87,25.4
  Top 0.406: v19.99,29.21 19.99,33.66 18.72,34.92 18.72,37.78 | 75.87,25.4 80.95,20.32 80.95,12.7 v82.22,12.7
  Bottom 0.305: v19.99,29.21 21.26,30.48 25.39,30.48 27.29,32.38 40.31,32.38 40.31,29.84 44.75,29.84 46.02,31.11 68.25,31.11 70.15,33.02 72.69,33.02 v73.33,33.66
  Bottom 0.406: v82.22,12.7 82.22,8.26
  Bottom 1.27: 82.22,8.26 RSET.1 82.22,0.64
VCC  (via drill 0.8)
  Top 0.305: 73.33,21.59 68.25,21.59 66.98,20.32 64.76,20.32 64.76,20 | IC11.6 89.84,71.75 97.46,71.75 97.46,59.69 R24.1
  Top 0.406: 73.33,21.59 R33.1
  Top 1.016: R24.1 93.65,56.2 v93.65,51.44
  Top 1.27: v64.44,12.7 64.44,17.78 64.76,18.1 64.76,20 60.63,24.13 v60.63,25.4 | v23.8,21.59 21.26,24.13 21.26,27.3 v22.53,28.57 | IC3.16 0.94,21.59 0.94,34.29 v2.21,35.56 | 16.18,63.5 IC8.20 | 16.18,63.5 14.91,63.5 14.91,62.23 | 14.91,62.23 IC5.14 v14.91,48.26 | 14.91,62.23 16.18,63.5 | R28.2 2.21,72.39 4.75,72.39 4.75,74.93 | 4.75,74.93 4.75,80.01 0.94,80.01 0.94,93.66 13.64,93.66 | 4.75,74.93 IC1.14 | C22.1 IC7.5 v13.64,35.56 | IC5.4 v22.53,48.26 | R14.1 13.64,77.47 13.64,93.66 | R12.1 36.5,74.93 33.96,77.47 33.96,93.66 13.64,93.66
  Bottom 1.016: R10.1 41.58,69.22 36.5,69.22 R12.1
  Bottom 1.27: 64.44,0.64 27-VCC.1 64.44,8.26 v64.44,12.7 | v23.8,21.59 IC12.14 | 3.48,38.73 3.48,36.83 v2.21,35.56 | 3.48,38.73 IC7.14 | 54.6,25.4 IC6.12 51.74,28.57 v22.53,28.57 21.26,27.3 13.64,27.3 C22.1 | 54.6,25.4 v60.63,25.4 | IC8.20 R28.2 | 35.23,48.26 v22.53,48.26 v14.91,48.26 | 3.48,38.73 6.02,38.73 | 6.02,38.73 11.1,38.73 | 11.1,38.73 13.64,38.73 | 13.64,38.73 19.35,38.73 22.53,41.91 IC5.4 | 13.64,38.73 v13.64,35.56 | 6.02,38.73 IC7.13 | 11.1,38.73 IC7.11 | 54.6,25.4 54.6,29.84 68.88,29.84 70.79,31.75 74.6,31.75 77.14,34.29 | 77.14,34.29 R4.1 | 77.14,34.29 IC2.10 | 35.23,48.26 IC4.14 | 35.23,48.26 45.39,48.26 46.02,48.9 51.74,48.9 54.91,52.07 60.63,52.07 60.63,48.26 74.6,48.26 77.77,51.44 v93.65,51.44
